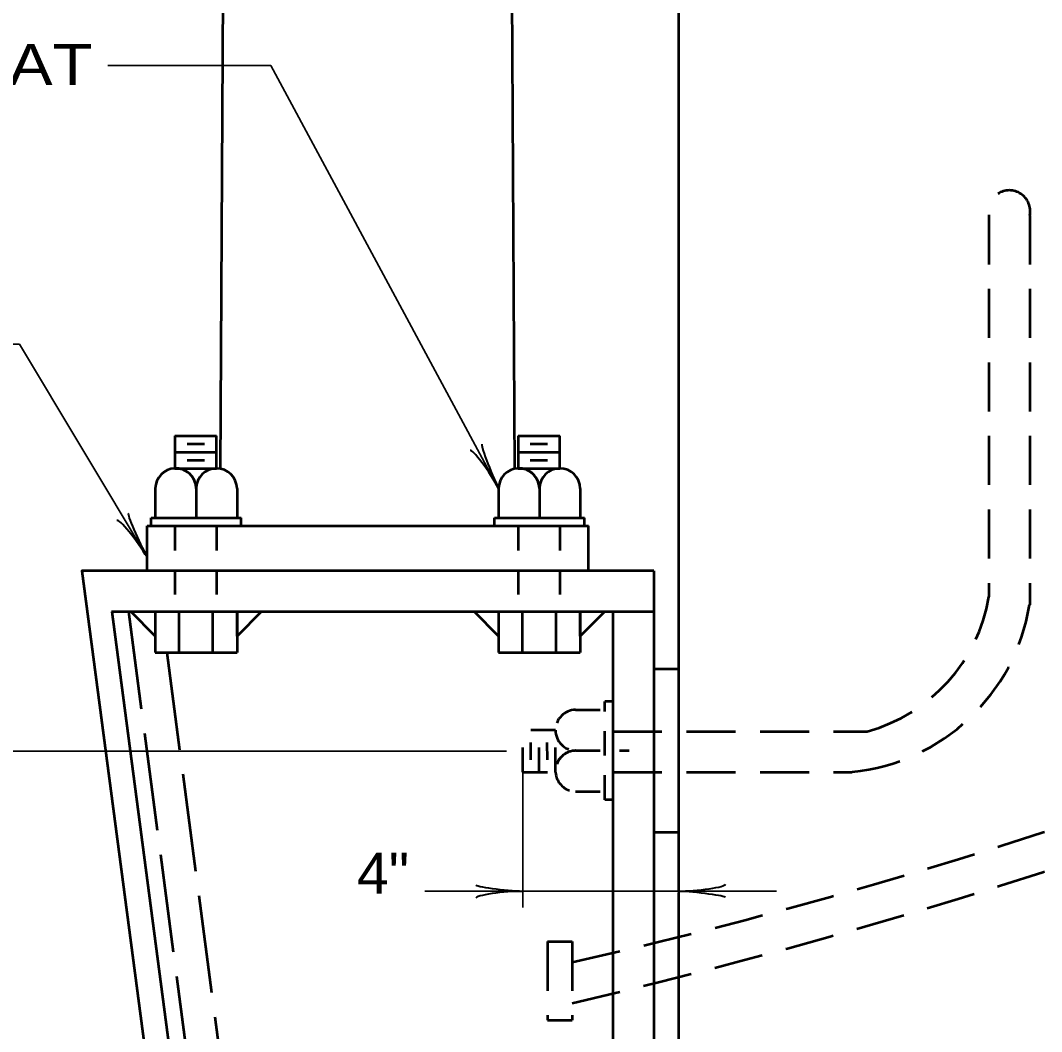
# Model space of a CAD drawing. Extents: x -1 to 679, y 0 to 440.
# Drawn here: x 276.1 to 338.6, y 111.9 to 173.8 of the extents above; entities that cross this region are included whole.
import ezdxf
from ezdxf.enums import TextEntityAlignment as Align

# ---------------------------------------------------------------- set-up
doc = ezdxf.new("R2010")
doc.units = 0
for name, pattern in [('LONG_DASHED', [7.5, 6, -1.5]), ('MEDIUM_DASHED', [4.5, 3, -1.5]), ('SHORT_DASHED', [2.7, 1.5, -1.2])]:
    doc.linetypes.add(name, pattern=pattern)
doc.layers.add('1', color=7, linetype='Continuous', lineweight=35)

msp = doc.modelspace()

# ---------------------------------------------------------------- linework, layer by layer
at = {"layer": '1', "lineweight": 53}
for p, q in [((288.843, 231.916), (288.34, 146.328)), ((305.843, 231.916), (306.347, 146.303)), ((316.37, 189.85), (316.37, 120.49)), ((285.561, 148.366), (288.12, 148.367)), ((285.561, 148.366), (285.561, 146.366)), ((288.12, 146.367), (288.12, 148.367)), ((306.561, 148.366), (309.12, 148.367)), ((306.561, 148.366), (306.561, 146.366)), ((309.12, 146.367), (309.12, 148.367)), ((286.311, 147.866), (287.371, 147.867)), ((307.311, 147.866), (308.371, 147.867)), ((285.562, 147.366), (288.121, 147.367)), ((286.312, 146.866), (287.371, 146.867)), ((306.562, 147.366), (309.121, 147.367)), ((307.312, 146.866), (308.371, 146.867)), ((285.561, 146.366), (288.12, 146.367)), ((285.561, 146.366), (288.12, 146.367)), ((306.561, 146.366), (309.12, 146.367)), ((306.561, 146.366), (309.12, 146.367)), ((284.37, 145.141), (284.37, 143.35)), ((286.87, 145.141), (286.87, 143.35)), ((289.37, 145.141), (289.37, 143.35)), ((305.37, 145.141), (305.37, 143.35)), ((307.87, 145.141), (307.87, 143.35)), ((310.37, 145.141), (310.37, 143.35)), ((284.12, 142.85), (284.12, 143.35)), ((284.12, 143.35), (289.62, 143.35)), ((289.62, 142.85), (289.62, 143.35)), ((305.12, 142.85), (305.12, 143.35)), ((305.12, 143.35), (310.62, 143.35)), ((310.62, 142.85), (310.62, 143.35)), ((283.87, 140.1), (283.87, 142.85)), ((283.87, 142.85), (310.87, 142.85)), ((310.87, 140.1), (310.87, 142.85)), ((314.87, 140.1), (314.87, 85.85)), ((281.713, 137.6), (287.446, 94.125)), ((284.37, 136.1), (282.87, 137.6)), ((284.37, 137.6), (284.37, 135.1)), ((285.811, 137.6), (285.811, 135.1)), ((287.87, 137.6), (287.87, 135.1)), ((289.37, 137.6), (289.37, 135.1)), ((289.37, 137.6), (306.561, 137.6)), ((303.87, 137.6), (310.37, 137.6)), ((305.37, 136.1), (303.87, 137.6)), ((305.37, 137.6), (305.37, 135.1)), ((306.811, 137.6), (314.87, 137.6)), ((306.811, 137.6), (306.811, 135.1)), ((308.87, 137.6), (308.87, 135.1)), ((310.37, 137.6), (310.37, 135.1)), ((312.37, 137.6), (312.37, 89.216)), ((284.37, 135.1), (289.37, 135.1)), ((305.37, 135.1), (310.37, 135.1)), ((314.87, 134.1), (316.37, 134.1)), ((314.87, 124.1), (316.37, 124.1)), ((316.37, 120.411), (316.37, 111.193))]:
    msp.add_line(p, q, dxfattribs=at)
at = {"layer": '1', "linetype": 'MEDIUM_DASHED', "lineweight": 53}
for p, q in [((335.37, 161.85), (335.37, 138.514)), ((337.87, 161.85), (337.87, 138.014)), ((312.37, 130.273), (327.932, 130.273)), ((312.37, 127.784), (327.011, 127.784)), ((308.37, 117.402), (308.37, 112.602)), ((308.37, 117.402), (309.87, 117.402)), ((309.87, 117.402), (309.87, 112.602)), ((308.37, 112.602), (309.87, 112.602))]:
    msp.add_line(p, q, dxfattribs=at)
at = {"layer": '1', "linetype": 'SHORT_DASHED', "lineweight": 53}
for p, q in [((285.561, 142.85), (285.561, 137.6)), ((288.12, 142.85), (288.12, 137.6)), ((306.561, 142.85), (306.561, 137.6)), ((309.12, 142.85), (309.12, 137.6)), ((312.37, 132.1), (311.87, 132.1)), ((310.079, 131.593), (311.87, 131.593)), ((308.853, 130.343), (306.853, 130.343)), ((306.855, 127.784), (306.853, 130.343)), ((307.855, 127.784), (307.853, 130.343)), ((308.855, 127.784), (308.853, 130.343)), ((308.855, 127.784), (308.853, 130.343)), ((307.355, 128.534), (307.354, 129.593)), ((308.355, 128.534), (308.354, 129.594)), ((310.079, 129.093), (313.37, 129.093)), ((306.855, 127.784), (308.855, 127.784)), ((310.079, 126.593), (311.87, 126.593))]:
    msp.add_line(p, q, dxfattribs=at)
at = {"layer": '1', "linetype": 'LONG_DASHED', "lineweight": 53}
for p, q in [((282.722, 137.6), (288.497, 93.808)), ((285.069, 135.1), (290.239, 95.894))]:
    msp.add_line(p, q, dxfattribs=at)
at = {"layer": '1'}
for p, q in [((305.854, 129.063), (268.854, 129.063)), ((306.855, 127.784), (306.855, 119.49)), ((300.855, 120.49), (306.855, 120.49))]:
    msp.add_line(p, q, dxfattribs=at)
for points in [[(305.37, 145.141), (291.436, 171.016), (281.459, 171.016)], [(283.87, 140.936), (276.055, 153.966), (270.027, 153.966)], [(306.855, 120.49), (316.37, 120.49), (322.37, 120.49)]]:
    msp.add_lwpolyline(points, dxfattribs=at)
at = {"layer": '1', "lineweight": 53}
for points in [[(314.87, 140.1), (279.87, 140.1), (285.87, 94.6), (314.87, 85.85)], [(281.7, 137.6), (282.87, 137.6), (289.37, 137.6)], [(282.722, 137.6), (284.37, 137.6), (284.37, 136.1)], [(303.722, 137.6), (305.37, 137.6), (305.37, 136.1)]]:
    msp.add_lwpolyline(points, dxfattribs=at)
for points in [[(289.37, 136.1), (289.37, 137.6), (290.87, 137.6)], [(310.37, 136.1), (310.37, 137.6), (311.87, 137.6)]]:
    msp.add_lwpolyline(points, close=True, dxfattribs=at)
at = {"layer": '1', "linetype": 'SHORT_DASHED', "lineweight": 53}
msp.add_lwpolyline([(312.37, 126.09), (311.87, 126.09), (311.87, 132.1)], dxfattribs=at)
at = {"layer": '1', "linetype": 'MEDIUM_DASHED', "lineweight": 53}
for centre, radius, start, end in [((336.621, 162.108), 1.276, 348.35602, 191.64398), ((325.201, 140.215), 10.315, 285.35044, 350.50977), ((325.752, 139.984), 12.263, 275.89125, 350.75456), ((237.574, 434.084), 326.063, 282.8105, 290.45715), ((227.003, 466.974), 362.924, 283.19898, 290.06715)]:
    msp.add_arc(centre, radius, start, end, dxfattribs=at)
at = {"layer": '1', "lineweight": 53}
for centre, start, end in [((285.62, 145.117), 92.7125, 178.88668), ((285.62, 145.117), 1.11332, 92.7125), ((285.62, 145.117), 1.11332, 87.2875), ((288.12, 145.117), 90, 178.88668), ((288.12, 145.117), 90, 178.88668), ((288.12, 145.117), 1.11332, 90), ((306.62, 145.117), 92.7125, 178.88668), ((306.62, 145.117), 1.11332, 92.7125), ((306.62, 145.117), 1.11332, 87.2875), ((309.12, 145.117), 90, 178.88668), ((309.12, 145.117), 90, 178.88668), ((309.12, 145.117), 1.11332, 90)]:
    msp.add_arc(centre, 1.25, start, end, dxfattribs=at)
at = {"layer": '1', "linetype": 'SHORT_DASHED', "lineweight": 53}
for centre, start, end in [((310.104, 130.343), 91.11332, 180), ((310.104, 130.343), 180, 268.88668), ((310.104, 130.343), 180, 268.88668), ((310.104, 127.843), 91.11332, 182.7125), ((310.104, 127.843), 91.11332, 177.2875), ((310.104, 127.843), 182.7125, 268.88668)]:
    msp.add_arc(centre, 1.25, start, end, dxfattribs=at)
at = {"layer": '1', "lineweight": 40}
for centre, major_axis, ratio, start_param, end_param in [((304.61, 145.971), (0.984, -1.498), 0.122415, 0.896353, 3.141593), ((305.026, 146.228), (-0.678, 1.63), 0.07063, 6.282307, 8.559703), ((283.072, 141.73), (1.052, -1.451), 0.122415, 0.896353, 3.141593), ((283.476, 142.006), (0.753, -1.597), 0.07063, 3.140715, 5.41811), ((305.734, 120.701), (1.756, -0.176), 0.07063, 3.140715, 5.41811), ((305.734, 120.701), (1.756, -0.176), 0.07063, 3.140715, 5.41811), ((317.462, 120.766), (-1.786, -0.156), 0.122415, 0.896353, 3.141593), ((305.764, 120.213), (1.786, 0.156), 0.122415, 0.896353, 3.141593), ((305.764, 120.213), (1.786, 0.156), 0.122415, 0.896353, 3.141593), ((317.491, 120.278), (-1.756, 0.176), 0.07063, 3.140715, 5.41811)]:
    msp.add_ellipse(centre, major_axis=major_axis, ratio=ratio, start_param=start_param, end_param=end_param, dxfattribs=at)

# ---------------------------------------------------------------- texts
at = {"layer": '1', "width": 1.2}
msp.add_text('HEX NUT AND FLAT', height=2.5, dxfattribs=at).set_placement((261.477, 169.836), align=Align.CENTER)
at = {"layer": '1', "width": 1.05}
msp.add_text('4"', height=2.5, dxfattribs=at).set_placement((296.701, 120.34))

doc.saveas('drawing.dxf')
